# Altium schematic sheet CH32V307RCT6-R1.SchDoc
size 406 x 281 mm; SheetNumber: 0; SheetTotal: 0
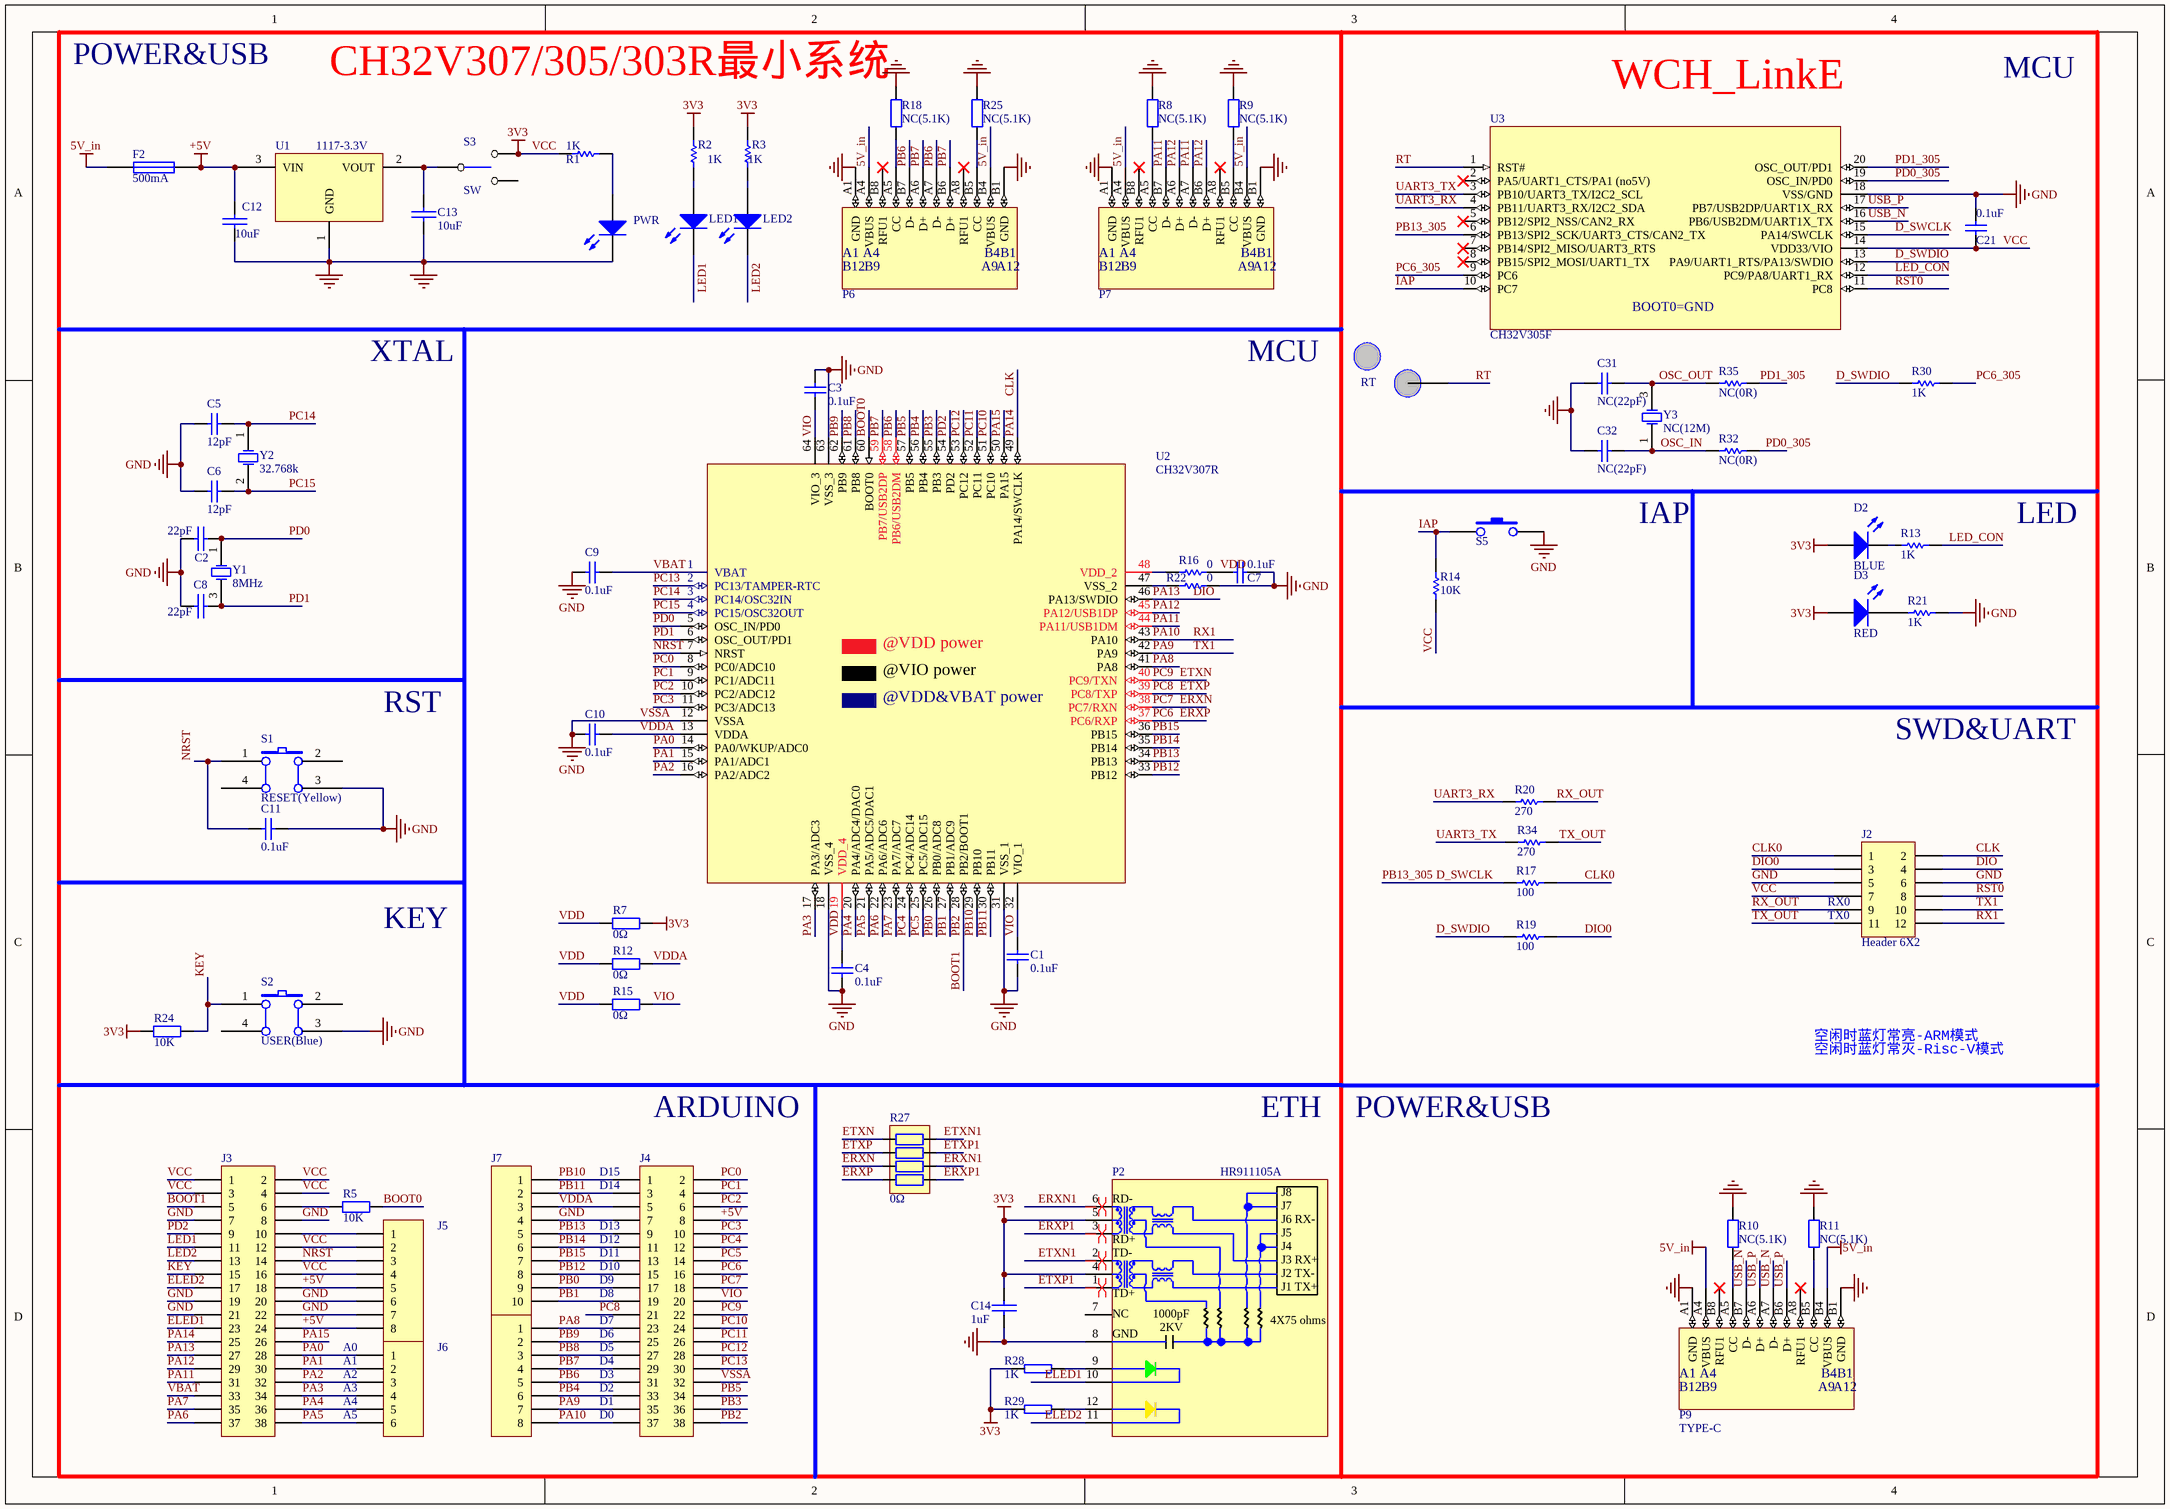
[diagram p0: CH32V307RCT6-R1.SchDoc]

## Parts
C1  0.1uF  [0603_C]
C2  22pF  [0603_C]
C3  0.1uF  [0603_C]
C4  0.1uF  [0603_C]
C5  12pF  [0603_C]
C6  12pF  [0603_C]
C7  0.1uF  [0603_C]
C8  22pF  [0603_C]
C9  0.1uF  [0603_C]
C10  0.1uF  [0603_C]
C11  0.1uF  [0603_C]
C12  10uF  [3216_C]
C13  10uF  [3216_C]
C14  1uF  [0603_C]
C21  0.1uF  [0603_C]
C31  NC(22pF)  [0603_C]
C32  NC(22pF)  [0603_C]
D2  BLUE  [0603+]
D3  RED  [0603+]
F2  500mA  [0805]
J2  Header 6X2  [IDC12-2.54mm]
J3  Header 19X2  [IDC38-2.54mm]  (value not drawn)
J4  Header 19X2  [IDC38-2.54mm]  (value not drawn)
J5  Header 8  [SIP8-2.54mm]  (value not drawn)
J6  Header 6  [SIP6-2.54MM]  (value not drawn)
J7  Header 10  [SIP10-2.54mm]  (value not drawn)
J8  Header 8  [SIP8-2.54mm]  (value not drawn)
LED1  LED1   blue  [0603+]  (value not drawn)
LED2  LED2  blue  [0603+]  (value not drawn)
P2  HR911105A  [HR911105A]
P6  TYPE-C  [TYPE-C-Receptacle-2.0]  (value not drawn)
P7  TYPE-C  [TYPE-C-Receptacle-2.0]  (value not drawn)
P9  TYPE-C  [TYPE-C-Receptacle-2.0]
PWR  POWER  red  [0603+]  (value not drawn)
R1  1K  [0603]
R2  1K  [0603]
R3  1K  [0603]
R5  10K  [0603]
R7  0Ω  [0603]
R8  NC(5.1K)  [0603]
R9  NC(5.1K)  [0603]
R10  NC(5.1K)  [0603]
R11  NC(5.1K)  [0603]
R12  0Ω  [0603]
R13  1K  [0603]
R14  10K  [0603]
R15  0Ω  [0603]
R16  0  [0603]
R17  100  [0603]
R18  NC(5.1K)  [0603]
R19  100  [0603]
R20  270  [0603]
R21  1K  [0603]
R22  0  [0603]
R24  10K  [0603]
R25  NC(5.1K)  [0603]
R27  0Ω  [8P4R-0603]
R28  1K  [0603]
R29  1K  [0603]
R30  1K  [0603]
R32  NC(0R)  [0603]
R34  270  [0603]
R35  NC(0R)  [0603]
RT  Testpoint  [TESTPOINT1]  (value not drawn)
S1  RESET(Yellow)  [KEYX]
S2  USER(Blue)  [KEYX]
S3  SW  [SW1]
S5  KEY  [贴片按键]  (value not drawn)
U1  1117-3.3V  [SOT-223]
U2  CH32V307R  [LQFP64M_10x10]
U3  CH32V305F  [TSSOP20]
Y1  8MHz  [XT3225]
Y2  32.768k  [FC-135]
Y3  NC(12M)  [XT3225]

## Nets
5V_in: F2.1 P6.A4(VBUS) P6.B4(VBUS) P7.A4(VBUS) P7.B4(VBUS) P9.A4(VBUS) P9.B4(VBUS)
+5V: C12.1 F2.2 J3.18 J3.24 J4.8 J5.5 J5.8 U1.3(VIN)
GND: C1.1 C2.1 C3.1 C4.1 C5.2 C6.2 C7.1 C8.1 C9.2 C10.2 C11.1 C12.2 C13.2 C14.1 C21.2 C31.1 C32.1 J2.5 J2.6 J3.7 J3.8 J3.19 J3.20 J3.21 J3.22 J4.7 J4.32 J5.6 J5.7 J7.4 P2.8 P6.A1(GND) P6.B1(GND) P7.A1(GND) P7.B1(GND) P9.A1(GND) P9.B1(GND) PWR.2(K) R8.1 R9.1 R10.2 R11.2 R18.1 R21.1 R22.1 R25.1 S1.3(B1) S2.3(B1) S5.2 U1.1(GND) U2.12(VSSA) U2.18(VSS_4) U2.31(VSS_1) U2.63(VSS_3) U3.18(VSS/GND)  [also labelled VSSA]
VCC: C14.2 C21.1 D2.1(A) D3.1(A) J2.7 J3.1 J3.2 J3.3 J3.4 J3.12 J3.16 J5.2 J5.4 P2.4 P2.5 R1.2 R2.1 R3.1 R7.1 R14.2 R24.2 R28.1 R29.1 S3.3 U3.14(VDD33/VIO)  [also labelled 3V3]
BOOT0: R5.2 U2.60(BOOT0)
BOOT1: J3.5 J4.38 U2.28(PB2/BOOT1)  [also labelled PB2]
CLK: J2.2 J3.25 U2.49(PA14/SWCLK)  [also labelled PA14]
CLK0: J2.1 R17.1
D_SWCLK: R17.2 U3.6(PB13/SPI2_SCK/UART3_CTS/CAN2_TX) U3.15(PA14/SWCLK)  [also labelled PB13_305]
D_SWDIO: R19.2 R30.1 U3.13(PA9/UART1_RTS/PA13/SWDIO)
DIO: J2.4 J3.27 U2.46(PA13/SWDIO)  [also labelled PA13]
DIO0: J2.3 R19.1
ELED1: J3.23 P2.10
ELED2: J3.17 P2.11
ERXN: J4.18 R27.3 U2.38(PC7/RXN)  [also labelled PC7]
ERXN1: P2.6 R27.6
ERXP: J4.16 R27.4 U2.37(PC6/RXP)  [also labelled PC6]
ERXP1: P2.3 R27.5
ETXN: J4.22 R27.1 U2.40(PC9/TXN)  [also labelled PC9]
ETXN1: P2.2 R27.8
ETXP: J4.21 R27.2 U2.39(PC8/TXP)  [also labelled PC8]
ETXP1: P2.1 R27.7
IAP: R14.1 S5.1 U3.10(PC7)
KEY: J3.15 R24.1 S2.1(A0)
LED1: J3.11 LED1.2(K)
LED2: J3.13 LED2.2(K)
LED_CON: R13.1 U3.12(PC9/PA8/UART1_RX)
NRST: C11.2 J3.14 J5.3 S1.1(A0) U2.7(NRST)
OSC_IN: C32.2 R32.2 Y3.1(OSC1)
OSC_OUT: C31.2 R35.2 Y3.3(OSC2)
PA0: J3.28 J6.1 U2.14(PA0/WKUP/ADC0)
PA1: J3.30 J6.2 U2.15(PA1/ADC1)
PA2: J3.32 J6.3 U2.16(PA2/ADC2)
PA3: J3.34 J6.4 U2.17(PA3/ADC3)
PA4: J3.36 J6.5 U2.20(PA4/ADC4/DAC0)
PA5: J3.38 J6.6 U2.21(PA5/ADC5/DAC1)
PA6: J3.37 U2.22(PA6/ADC6)
PA7: J3.35 U2.23(PA7/ADC7)
PA8: J4.23 J8.1 U2.41(PA8)
PA9: J2.10 J4.35 J8.7 U2.42(PA9)  [also labelled TX1]
PA10: J2.12 J4.37 J8.8 U2.43(PA10)  [also labelled RX1]
PA11: J3.31 P7.A7(D-) P7.B7(D-) U2.44(PA11/USB1DM)
PA12: J3.29 P7.A6(D+) P7.B6(D+) U2.45(PA12/USB1DP)
PA15: J3.26 U2.50(PA15)
PB0: J4.17 J7.9 U2.26(PB0/ADC8)
PB1: J4.19 J7.10 U2.27(PB1/ADC9)
PB3: J4.36 U2.55(PB3)
PB4: J4.33 J8.6 U2.56(PB4)
PB5: J4.34 U2.57(PB5)
PB6: J4.31 J8.5 P6.A7(D-) P6.B7(D-) U2.58(PB6/USB2DM)
PB7: J4.29 J8.4 P6.A6(D+) P6.B6(D+) U2.59(PB7/USB2DP)
PB8: J4.27 J8.3 U2.61(PB8)
PB9: J4.25 J8.2 U2.62(PB9)
PB10: J4.1 J7.1 U2.29(PB10)
PB11: J4.3 J7.2 U2.30(PB11)
PB12: J4.15 J7.8 U2.33(PB12)
PB13: J4.9 J7.5 U2.34(PB13)
PB14: J4.11 J7.6 U2.35(PB14)
PB15: J4.13 J7.7 U2.36(PB15)
PC0: J4.2 U2.8(PC0/ADC10)
PC1: J4.4 U2.9(PC1/ADC11)
PC2: J4.6 U2.10(PC2/ADC12)
PC3: J4.10 U2.11(PC3/ADC13)
PC4: J4.12 U2.24(PC4/ADC14)
PC5: J4.14 U2.25(PC5/ADC15)
PC6_305: R30.2 U3.9(PC6)
PC10: J4.24 U2.51(PC10)
PC11: J4.26 U2.52(PC11)
PC12: J4.28 U2.53(PC12)
PC13: J4.30 U2.2(PC13/TAMPER-RTC)
PC14: C5.1 U2.3(PC14/OSC32IN) Y2.1(OSC1)
PC15: C6.1 U2.4(PC15/OSC32OUT) Y2.2(OSC2)
PD0: C2.2 U2.5(OSC_IN/PD0) Y1.1(OSC1)
PD0_305: R32.1 U3.19(OSC_IN/PD0)
PD1: C8.2 U2.6(OSC_OUT/PD1) Y1.3(OSC2)
PD1_305: R35.1 U3.20(OSC_OUT/PD1)
PD2: J3.9 U2.54(PD2)
RST0: J2.8 U3.11(PC8)
RT: RT.1(point) U3.1(RST#)
RX_OUT: J2.9 R20.1
TX_OUT: J2.11 R34.1
UART3_RX: R20.2 U3.4(PB11/UART3_RX/I2C2_SDA)
UART3_TX: R34.2 U3.3(PB10/UART3_TX/I2C2_SCL)
USB_N: P9.A7(D-) P9.B7(D-) U3.16(PB6/USB2DM/UART1X_TX)
USB_P: P9.A6(D+) P9.B6(D+) U3.17(PB7/USB2DP/UART1X_RX)
VBAT: C9.1 J3.33 U2.1(VBAT)
VDD: C4.2 C7.2 R7.2 R12.2 R15.2 R16.1 U2.19(VDD_4)
VDDA: C10.1 J4.5 J7.3 R12.1 U2.13(VDDA)
VIO: C1.2 C3.2 J4.20 R15.1 U2.32(VIO_1) U2.64(VIO_3)
NetC13_1: C13.1 S3.1 U1.2(VOUT)
NetD2_2: D2.2(K) R13.2
NetD3_2: D3.2(K) R21.2
NetJ3_6: J3.6 R5.1
NetJ3_10: J3.10 J5.1
NetLED1_1: LED1.1(A) R2.2
NetLED2_1: LED2.1(A) R3.2
NetP2_9: P2.9 R28.2
NetP2_12: P2.12 R29.2
NetP6_A5: P6.A5(CC) R18.2
NetP6_B5: P6.B5(CC) R25.2
NetP7_A5: P7.A5(CC) R8.2
NetP7_B5: P7.B5(CC) R9.2
NetP9_A5: P9.A5(CC) R10.1
NetP9_B5: P9.B5(CC) R11.1
NetPWR_1: PWR.1(A) R1.1
NetR16_2: R16.2 U2.48(VDD_2)
NetR22_2: R22.2 U2.47(VSS_2)

Not connected (* = marked no-connect by the designer): P2 7; P6 A8(RFU1)* B8(RFU1)*; P7 A8(RFU1)* B8(RFU1)*; P9 A8(RFU1)* B8(RFU1)*; S1 2(B0) 4(A1); S2 2(B0) 4(A1); S3 2; U3 2(PA5/UART1_CTS/PA1_(no5V))* 5(PB12/SPI2_NSS/CAN2_RX)* 7(PB14/SPI2_MISO/UART3_RTS)* 8(PB15/SPI2_MOSI/UART1_TX)*

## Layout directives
differential pair: ERXN1, ERXP1, ETXN1, ETXP1

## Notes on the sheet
- POWER&USB
- CH32V307/305/303R最小系统
- WCH_LinkE
- MCU
- XTAL
- IAP
- LED
- RST
- SWD&UART
- (near J2) RX0
- (near J2) TX0
- KEY
- 空闲时蓝灯常亮-ARM模式
- 空闲时蓝灯常灭-Risc-V模式
- ARDUINO
- ETH
- (near J4) D14
- (near J4) D15
- (near J4) D11
- (near J4) D12
- (near J4) D13
- (near J4) D7
- (near J4) D8
- (near J4) D9
- (near J4) D10
- A0
- A1
- (near J6) A2
- (near J6) A3
- (near J4) D2
- (near J4) D3
- (near J4) D4
- (near J4) D5
- (near J4) D6
- (near J6) A4
- (near J6) A5
- (near J4) D0
- (near J4) D1

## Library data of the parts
C1 C3-C7 C9-C11 C21 C31 C32 = Cap: Capacitor
C2 C8 C12-C14 = CAP: Capacitor
D2 D3 = D0603: Typical RED, GREEN, YELLOW, AMBER GaAs LED
F2 = FUSE1: Fuse
J2 = Header 6X2: Header, 6-Pin, Dual row
J3 J4 = Header 19X2: Header, 19-Pin, Dual row
J5 J8 = Header 8: Header, 8-Pin
J6 = Header 6: Header, 6-Pin
J7 = Header 10: Header, 10-Pin
LED1 LED2 PWR = LED0: Typical INFRARED GaAs LED
P6 P7 P9 = TYPE-C1
R1-R3 = Res Semi: Semiconductor Resistor
R5 R7-R12 R15 R18 R24 R25 = Res2: Resistor
R13 R14 R16 R17 R19-R22 R30 R32 R34 R35 = R0603: Resistor
R27 = R-8P4R: 贴片网络排阻; 版权归属: 源创客
R28 R29 = RES
RT = Testpoint: 测试点
S1 S2 = SW PUSHBUTTON: SE PUSHBUTTON
U2 = CH32V307R: RISC-V FPU HD-MCU, 144MHz, USB_480M, USB OTG, 1000M Ethernet MAC, 2*CAN
U3 = CH32V305F: RISC-V FPU HD-MCU, 144MHz, USB_480M, CAN, UART*2, SPI
Y1-Y3 = XTAL: Crystal Oscillator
